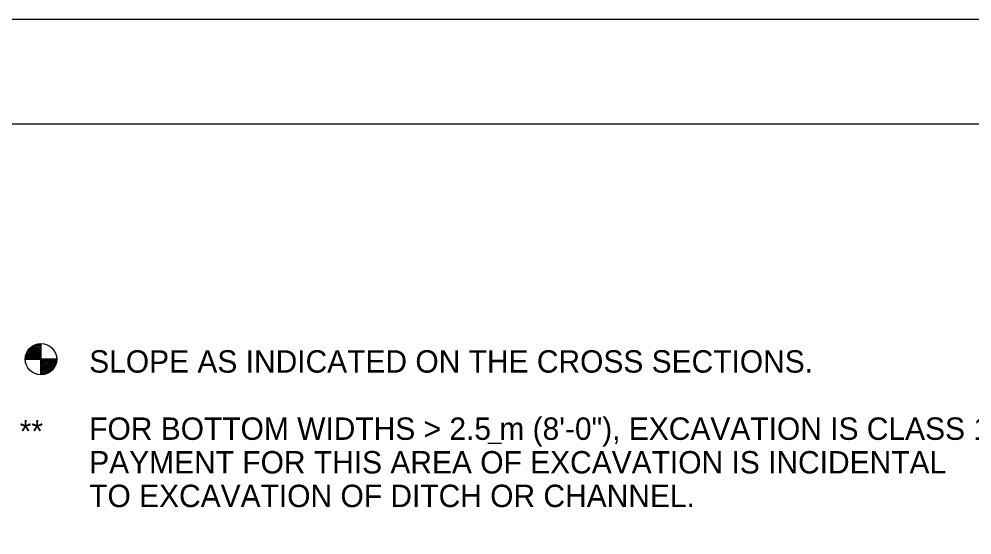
# Model space of a CAD drawing. Extents: x 240 to 1147, y 662 to 1256.
# Drawn here: x 760.7 to 896.9, y 1182.3 to 1256 of the extents above; entities that cross this region are included whole.
import ezdxf

# ---------------------------------------------------------------- set-up
doc = ezdxf.new("R2010")
doc.units = 0
for name, color, linetype in [('1', 7, 'Continuous'), ('2', 7, 'Continuous'), ('3', 7, 'Continuous'), ('PLT-BNDY', 7, 'Continuous')]:
    doc.layers.add(name, color=color, linetype=linetype)

msp = doc.modelspace()

# ---------------------------------------------------------------- linework, layer by layer
at = {"layer": '1'}
msp.add_lwpolyline([(1065.4425, 677.018625), (1065.4425, 1241.018625), (279.4425, 1241.018625), (279.4425, 677.018625), (1065.4425, 677.018625), (1065.4425, 703.377625), (865.4425, 703.377625), (865.4425, 768.055125), (1065.4425, 768.055125), (1065.4425, 797.018625), (865.4425, 797.018625), (865.4425, 677.018625), (944.244, 677.018625), (944.244, 703.377625), (944.244, 677.018625), (1021.244, 677.018625), (1021.244, 703.377625), (1021.244, 691.061125), (1065.4425, 691.061125)], dxfattribs=at)
at = {"layer": '2'}
for p, q in [((763.831, 1205.201125), (763.831, 1209.690625)), ((763.831, 1205.201125), (763.831, 1209.690625)), ((763.831, 1209.688625), (763.831, 1205.198875)), ((763.831, 1209.688625), (763.831, 1205.198875)), ((766.07475, 1207.446875), (761.58525, 1207.446875)), ((766.07475, 1207.444875), (761.58525, 1207.444875)), ((761.58725, 1207.446875), (766.07675, 1207.446875)), ((761.58725, 1207.444875), (766.07675, 1207.444875)), ((827.66425, 1195.467625), (829.654, 1195.467625))]:
    msp.add_line(p, q, dxfattribs=at)
for points in [[(763.82275, 1209.569875), (763.53525, 1209.553125), (763.2685, 1209.484375), (763.0205, 1209.405125), (762.76425, 1209.280125), (762.5205, 1209.126125), (762.2935, 1208.934375), (762.1185, 1208.717625), (761.9435, 1208.451125), (761.82675, 1208.186375), (761.73525, 1207.896875), (761.6955, 1207.636375), (761.6915, 1207.438625)], [(763.82475, 1209.411375), (763.56025, 1209.394875), (763.31225, 1209.332375), (763.079, 1209.257375), (762.8435, 1209.142625), (762.6165, 1208.996875), (762.408, 1208.821875), (762.24775, 1208.623875), (762.083, 1208.373875), (761.97675, 1208.130125), (761.8915, 1207.859375), (761.854, 1207.621875), (761.84975, 1207.438625)], [(763.82475, 1209.251125), (763.58525, 1209.236375), (763.356, 1209.178125), (763.13925, 1209.107375), (762.9205, 1209.003125), (762.71025, 1208.867625), (762.52275, 1208.709375), (762.37675, 1208.530125), (762.22475, 1208.298875), (762.12675, 1208.073875), (762.04775, 1207.823875), (762.01425, 1207.609375), (762.01025, 1207.438625)], [(763.82475, 1209.090625), (763.61025, 1209.078125), (763.39975, 1209.023875), (763.19975, 1208.959375), (762.99975, 1208.863625), (762.806, 1208.738625), (762.63725, 1208.596875), (762.504, 1208.434375), (762.36425, 1208.221875), (762.27475, 1208.019875), (762.20175, 1207.786375), (762.17275, 1207.594875), (762.1685, 1207.438625)], [(763.82475, 1208.932375), (763.63525, 1208.919875), (763.4455, 1208.871875), (763.258, 1208.811375), (763.07675, 1208.723875), (762.89975, 1208.611375), (762.74975, 1208.484375), (762.633, 1208.340625), (762.506, 1208.144875), (762.42475, 1207.961375), (762.358, 1207.751125), (762.333, 1207.580125), (762.329, 1207.438625)], [(763.82475, 1208.771875), (763.66025, 1208.761375), (763.48925, 1208.717625), (763.3185, 1208.663625), (763.156, 1208.584375), (762.9955, 1208.482375), (762.86425, 1208.371875), (762.76225, 1208.246875), (762.6455, 1208.067625), (762.57475, 1207.905125), (762.51425, 1207.713625), (762.4915, 1207.567625), (762.48725, 1207.438625)], [(763.82475, 1208.611375), (763.68525, 1208.603125), (763.533, 1208.565625), (763.37675, 1208.515625), (763.233, 1208.444875), (763.08925, 1208.353125), (762.979, 1208.259375), (762.8915, 1208.153125), (762.78725, 1207.992625), (762.72275, 1207.851125), (762.6705, 1207.678125), (762.64975, 1207.553125), (762.64775, 1207.438625)], [(763.82475, 1208.453125), (763.708, 1208.444875), (763.57675, 1208.411375), (763.43725, 1208.365625), (763.31025, 1208.305125), (763.18525, 1208.223875), (763.0935, 1208.146875), (763.0205, 1208.057375), (762.92675, 1207.915625), (762.87275, 1207.794875), (762.82475, 1207.642625), (762.81025, 1207.538625), (762.808, 1207.438625)], [(763.82475, 1208.292625), (763.733, 1208.286375), (763.6205, 1208.257375), (763.49775, 1208.217625), (763.38925, 1208.165625), (763.279, 1208.094875), (763.208, 1208.036375), (763.14775, 1207.963625), (763.0665, 1207.840625), (763.02275, 1207.738625), (762.981, 1207.605125), (762.9685, 1207.523875), (762.9665, 1207.438625)], [(763.82475, 1208.132375), (763.758, 1208.128125), (763.6665, 1208.105125), (763.556, 1208.069875), (763.4665, 1208.026125), (763.37275, 1207.967625), (763.32275, 1207.923875), (763.27675, 1207.869875), (763.208, 1207.763625), (763.17275, 1207.682375), (763.13725, 1207.569875), (763.129, 1207.511375), (763.12675, 1207.438625)], [(763.82475, 1207.973875), (763.783, 1207.969875), (763.71025, 1207.951125), (763.6165, 1207.921875), (763.5455, 1207.886375), (763.4685, 1207.838625), (763.43525, 1207.811375), (763.406, 1207.773875), (763.34775, 1207.686375), (763.32275, 1207.626125), (763.2935, 1207.532375), (763.28725, 1207.496875), (763.28525, 1207.438625)], [(763.454, 1207.444875), (763.456, 1207.461375), (763.4705, 1207.513625), (763.4955, 1207.592625), (763.5205, 1207.644875), (763.558, 1207.705125), (763.5705, 1207.717625), (763.58725, 1207.732375), (763.658, 1207.780125), (763.69975, 1207.796875), (763.7705, 1207.819875), (763.78525, 1207.821875), (763.831, 1207.823875)], [(763.82475, 1207.651125), (763.79775, 1207.644875), (763.73525, 1207.623875), (763.69975, 1207.607375), (763.66225, 1207.584375), (763.629, 1207.534375), (763.6205, 1207.513625), (763.606, 1207.463625), (763.604, 1207.438625)], [(763.78725, 1207.436375), (763.78725, 1207.467625), (763.7915, 1207.484375), (763.7915, 1207.486375), (763.79975, 1207.496875), (763.79975, 1207.496875), (763.8165, 1207.507375), (763.8165, 1207.507375)], [(764.208, 1207.446875), (764.206, 1207.430125), (764.1935, 1207.376125), (764.1685, 1207.296875), (764.1415, 1207.244875), (764.104, 1207.184375), (764.0935, 1207.171875), (764.07475, 1207.157375), (764.004, 1207.111375), (763.96425, 1207.092625), (763.8915, 1207.069875), (763.87675, 1207.067625), (763.831, 1207.067625)], [(763.83925, 1205.319875), (764.12675, 1205.338625), (764.3955, 1205.405125), (764.6415, 1205.486375), (764.89775, 1205.609375), (765.1415, 1205.765625), (765.3685, 1205.957375), (765.5435, 1206.171875), (765.7205, 1206.440625), (765.83525, 1206.703125), (765.92675, 1206.994875), (765.9665, 1207.253125), (765.97275, 1207.453125)], [(763.83925, 1205.480125), (764.10175, 1205.496875), (764.34975, 1205.559375), (764.583, 1205.634375), (764.8185, 1205.748875), (765.0455, 1205.892625), (765.254, 1206.069875), (765.41425, 1206.267625), (765.579, 1206.515625), (765.68725, 1206.759375), (765.7705, 1207.030125), (765.808, 1207.267625), (765.81225, 1207.453125)], [(763.83925, 1205.638625), (764.07675, 1205.655125), (764.306, 1205.713625), (764.52275, 1205.782375), (764.7415, 1205.888625), (764.95175, 1206.021875), (765.1415, 1206.182375), (765.28725, 1206.361375), (765.43925, 1206.592625), (765.53725, 1206.815625), (765.6165, 1207.067625), (765.64975, 1207.282375), (765.65175, 1207.453125)], [(763.83925, 1205.798875), (764.054, 1205.811375), (764.26225, 1205.865625), (764.46425, 1205.930125), (764.66425, 1206.028125), (764.856, 1206.151125), (765.02675, 1206.292625), (765.158, 1206.455125), (765.29775, 1206.669875), (765.38725, 1206.871875), (765.46025, 1207.103125), (765.48925, 1207.296875), (765.4935, 1207.453125)], [(763.83925, 1205.959375), (764.029, 1205.971875), (764.2185, 1206.019875), (764.404, 1206.078125), (764.58525, 1206.167625), (764.76225, 1206.280125), (764.91225, 1206.405125), (765.029, 1206.548875), (765.158, 1206.744875), (765.23725, 1206.928125), (765.304, 1207.140625), (765.331, 1207.309375), (765.333, 1207.453125)], [(763.83925, 1206.117625), (764.004, 1206.128125), (764.17475, 1206.171875), (764.3455, 1206.228125), (764.508, 1206.307375), (764.6685, 1206.409375), (764.79775, 1206.517625), (764.89975, 1206.644875), (765.0165, 1206.821875), (765.08725, 1206.984375), (765.14775, 1207.176125), (765.1705, 1207.323875), (765.17475, 1207.453125)], [(763.83925, 1206.278125), (763.979, 1206.286375), (764.129, 1206.326125), (764.28525, 1206.376125), (764.429, 1206.446875), (764.57275, 1206.536375), (764.683, 1206.630125), (764.7705, 1206.738625), (764.87675, 1206.898875), (764.93925, 1207.040625), (764.9935, 1207.211375), (765.01225, 1207.338625), (765.01425, 1207.453125)], [(763.83925, 1206.438625), (763.954, 1206.444875), (764.08525, 1206.478125), (764.22475, 1206.523875), (764.35175, 1206.584375), (764.479, 1206.665625), (764.5685, 1206.742625), (764.6435, 1206.832375), (764.73525, 1206.973875), (764.78925, 1207.096875), (764.83725, 1207.248875), (764.854, 1207.351125), (764.856, 1207.453125)], [(763.83925, 1206.598875), (763.929, 1206.603125), (764.0415, 1206.632375), (764.1665, 1206.671875), (764.27475, 1206.723875), (764.383, 1206.794875), (764.456, 1206.855125), (764.51425, 1206.926125), (764.5955, 1207.051125), (764.63925, 1207.153125), (764.681, 1207.284375), (764.6935, 1207.365625), (764.6955, 1207.453125)], [(763.83925, 1206.757375), (763.904, 1206.761375), (763.99775, 1206.786375), (764.106, 1206.819875), (764.1955, 1206.863625), (764.28925, 1206.923875), (764.3415, 1206.967625), (764.38525, 1207.021875), (764.454, 1207.126125), (764.4915, 1207.209375), (764.52475, 1207.321875), (764.53525, 1207.380125), (764.53725, 1207.453125)], [(763.83925, 1206.917625), (763.879, 1206.919875), (763.954, 1206.938625), (764.04775, 1206.969875), (764.1185, 1207.003125), (764.1935, 1207.053125), (764.22675, 1207.080125), (764.256, 1207.115625), (764.31425, 1207.203125), (764.3415, 1207.265625), (764.3705, 1207.357375), (764.37475, 1207.394875), (764.37675, 1207.453125)], [(763.83925, 1207.238625), (763.86425, 1207.244875), (763.929, 1207.265625), (763.96225, 1207.282375), (763.99975, 1207.307375), (764.033, 1207.355125), (764.0415, 1207.378125), (764.058, 1207.426125), (764.058, 1207.453125)], [(763.87675, 1207.453125), (763.87475, 1207.421875), (763.87275, 1207.405125), (763.8705, 1207.403125), (763.86225, 1207.394875), (763.86225, 1207.394875), (763.8455, 1207.382375), (763.8455, 1207.382375)]]:
    msp.add_lwpolyline(points, dxfattribs=at)
for centre in [(763.830512, 1207.446063), (763.830512, 1207.444469), (763.83217, 1207.446063), (763.83217, 1207.444469)]:
    msp.add_circle(centre, 2.24484, dxfattribs=at)
at = {"layer": 'PLT-BNDY'}
msp.add_lwpolyline([(240.4425, 1256.018625), (1081.4425, 1256.018625), (1081.4425, 662.018625), (240.4425, 662.018625)], close=True, dxfattribs=at)

# ---------------------------------------------------------------- texts
at = {"layer": '3'}
for s, p in [('SLOPE AS INDICATED ON THE CROSS SECTIONS.', (770.72675, 1205.519887)), ('**', (760.79775, 1195.542625)), ('FOR BOTTOM WIDTHS > 2.5 m (8\'-0"), EXCAVATION IS CLASS 1.', (770.72675, 1195.919913)), ('PAYMENT FOR THIS AREA OF EXCAVATION IS INCIDENTAL', (770.72675, 1191.119925)), ('TO EXCAVATION OF DITCH OR CHANNEL.', (770.72675, 1186.319937))]:
    msp.add_text(s, height=3.1999875, dxfattribs=at).set_placement(p)

doc.saveas('drawing.dxf')
